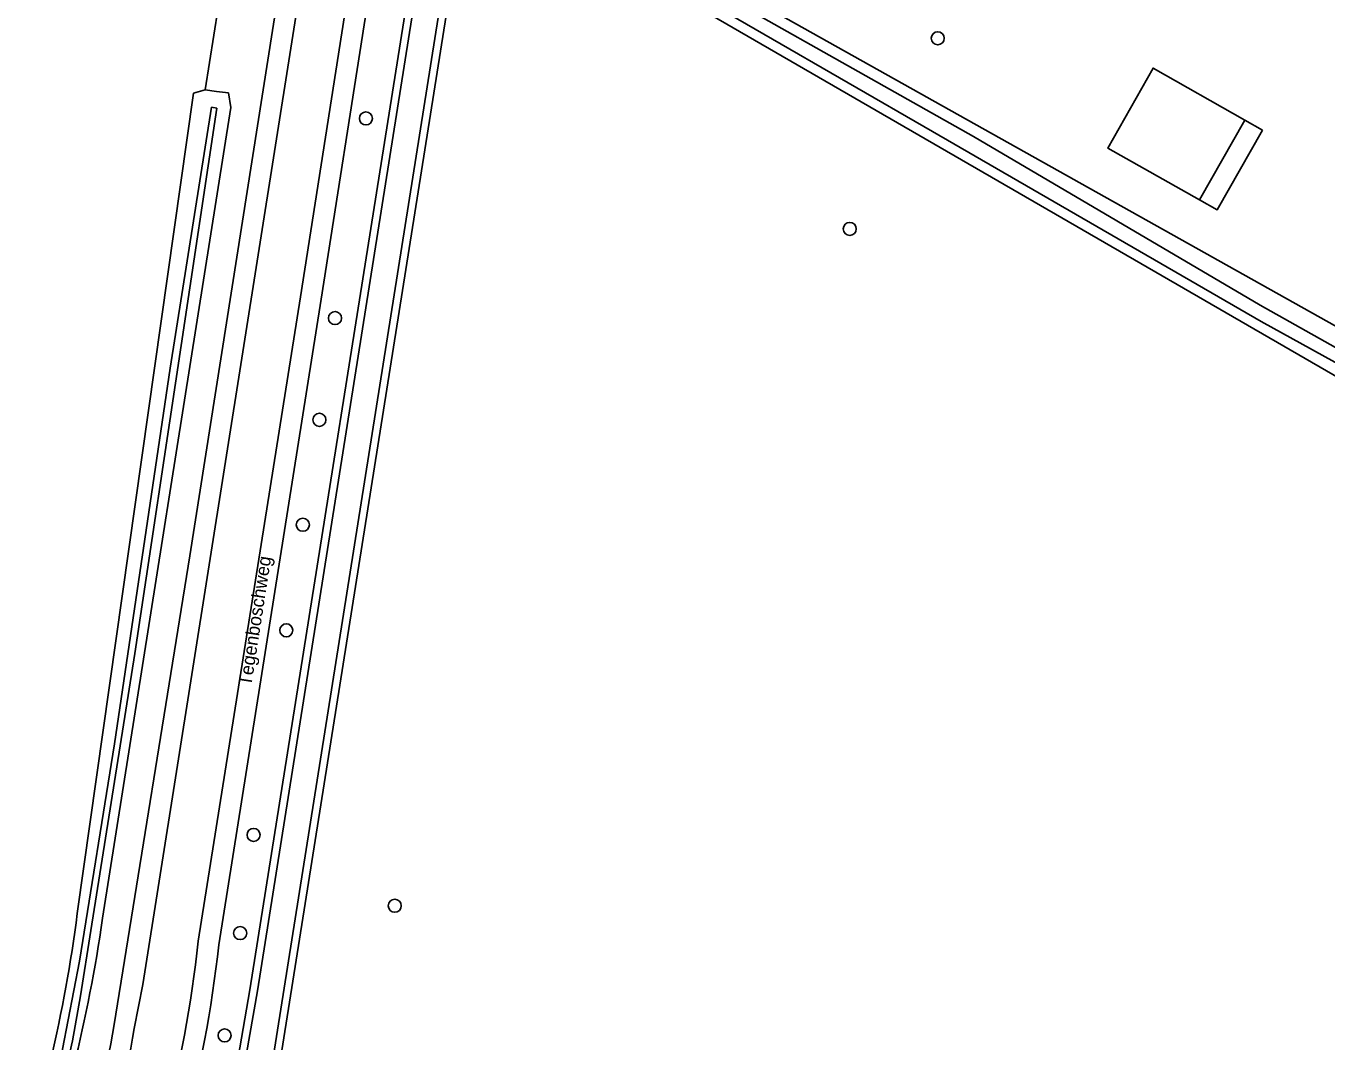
# Model space of a CAD drawing. Extents: x 156502 to 159074, y 384229 to 386094.
# Drawn here: x 157008.2 to 157105.6, y 385633.7 to 385709.8 of the extents above; entities that cross this region are included whole.
import ezdxf

# ---------------------------------------------------------------- set-up
doc = ezdxf.new("R2010")
doc.units = 0
for name, color, linetype in [('IMGEO_Berm_halfverhard', 7, 'Continuous'), ('IMGEO_Boom', 7, 'Continuous'), ('IMGEO_Erf', 7, 'Continuous'), ('IMGEO_Grasland_agrarisch', 7, 'Continuous'), ('IMGEO_Groenvoorziening', 7, 'Continuous'), ('IMGEO_Openbare_ruimte_label', 7, 'Continuous'), ('IMGEO_Pand', 7, 'Continuous'), ('IMGEO_Pand_overbouw', 7, 'Continuous'), ('IMGEO_Rijbaan_lokaal_gesloten', 7, 'Continuous'), ('IMGEO_Waterloop', 7, 'Continuous')]:
    doc.layers.add(name, color=color, linetype=linetype)

msp = doc.modelspace()

# ---------------------------------------------------------------- linework, layer by layer
at = {"layer": 'IMGEO_Berm_halfverhard'}
for points in [[(157022.679, 385641.008), (157030.346, 385689.372), (157037.17, 385733.031)], [(157029.081, 385724.73), (157020.509, 385670.144), (157014.848, 385635.051)]]:
    msp.add_lwpolyline(points, dxfattribs=at)
for centre, radius, start, end in [((156926.454, 385651.783), 96.827, 336.51688, 353.61054), ((156923.218, 385650.802), 92.974, 343.02444, 350.24631)]:
    msp.add_arc(centre, radius, start, end, dxfattribs=at)
at = {"layer": 'IMGEO_Boom'}
for centre in [(157076.496, 385708.898), (157033.686, 385702.902), (157069.905, 385694.625), (157031.374, 385687.945), (157030.203, 385680.329), (157028.966, 385672.472), (157027.729, 385664.568), (157025.277, 385649.249), (157035.849, 385643.947), (157024.275, 385641.895), (157023.112, 385634.236)]:
    msp.add_circle(centre, 0.489, dxfattribs=at)
at = {"layer": 'IMGEO_Erf'}
msp.add_lwpolyline([(157053.67, 385716.85), (157130.083, 385674.016), (157162.143, 385703.286), (157165.17, 385704.25)], dxfattribs=at)
at = {"layer": 'IMGEO_Grasland_agrarisch'}
for points in [[(157041.361, 385721.169), (157027.049, 385630.912), (157026.047, 385625.421)], [(157041.361, 385721.169), (157128.6, 385670.699)], [(157022.628, 385711.171), (157021.647, 385705.038)], [(157021.647, 385705.038), (157020.793, 385704.781), (157012.083, 385643.358)]]:
    msp.add_lwpolyline(points, dxfattribs=at)
msp.add_arc((156908.234, 385656.632), 104.693, 340.51833, 352.71601, dxfattribs=at)
at = {"layer": 'IMGEO_Groenvoorziening'}
for points in [[(157038.497, 385722.64), (157025.008, 385637.66), (157023.881, 385631.141)], [(157021.647, 385705.038), (157022.492, 385704.925), (157023.391, 385704.805), (157023.568, 385703.71), (157013.981, 385643.006)]]:
    msp.add_lwpolyline(points, dxfattribs=at)
msp.add_arc((156895.904, 385660.18), 119.319, 340.8403, 351.72454, dxfattribs=at)
at = {"layer": 'IMGEO_Pand'}
msp.add_lwpolyline([(157099.476, 385702.779), (157096.086, 385696.794), (157089.222, 385700.682), (157092.613, 385706.667), (157099.476, 385702.779)], dxfattribs=at)
at = {"layer": 'IMGEO_Pand_overbouw'}
msp.add_lwpolyline([(157100.798, 385702.03), (157099.476, 385702.779), (157096.086, 385696.794), (157097.408, 385696.045)], close=True, dxfattribs=at)
at = {"layer": 'IMGEO_Rijbaan_lokaal_gesloten'}
for points in [[(157021.135, 385641.291), (157028.792, 385689.543), (157035.621, 385733.246)], [(157029.365, 385716.4), (157016.981, 385638.047), (157016.346, 385634.756)]]:
    msp.add_lwpolyline(points, dxfattribs=at)
for centre, radius, start, end in [((156929.429, 385651.027), 92.222, 336.25729, 353.93976), ((156929.501, 385648.91), 87.991, 342.95976, 350.74323)]:
    msp.add_arc(centre, radius, start, end, dxfattribs=at)
at = {"layer": 'IMGEO_Waterloop'}
for points in [[(157041.24, 385723.767), (157041.2, 385723.209), (157041.602, 385722.806), (157053.036, 385716.305), (157079.167, 385701.542), (157100.636, 385688.921), (157128.657, 385673.175)], [(157040.743, 385720.856), (157026.496, 385631.006), (157025.499, 385625.542), (157023.426, 385618.899), (157020.73, 385612.483), (157017.435, 385606.354), (157013.57, 385600.567), (157003.902, 385586.956), (157002.01, 385584.431), (157000.304, 385585.596), (157002.021, 385588.237), (157006.901, 385594.494), (157011.059, 385599.905), (157014.753, 385605.643), (157017.958, 385611.667), (157020.651, 385617.937), (157022.814, 385624.409), (157024.433, 385631.038), (157025.562, 385637.568), (157038.93, 385721.787), (157040.743, 385720.856)], [(157128.318, 385672.451), (157100.715, 385687.7), (157076.092, 385701.913), (157050.852, 385716.529), (157040.926, 385722.25), (157040.55, 385722.131), (157040.422, 385721.651)], [(157022.12, 385703.749), (157019.028, 385684.205), (157014.87, 385656.071), (157012.251, 385639.805), (157010.559, 385631.006)], [(157010.691, 385629.362), (157011.729, 385633.841), (157012.332, 385637.197), (157013.1, 385642.095), (157016.4, 385662.831), (157019.86, 385685.902), (157022.52, 385703.662), (157022.12, 385703.749)]]:
    msp.add_lwpolyline(points, dxfattribs=at)

# ---------------------------------------------------------------- texts
at = {"layer": 'IMGEO_Openbare_ruimte_label'}
msp.add_text('Tegenboschweg', height=1, rotation=81.1972, dxfattribs=at).set_placement((157025.105, 385660.353))

doc.saveas('drawing.dxf')
